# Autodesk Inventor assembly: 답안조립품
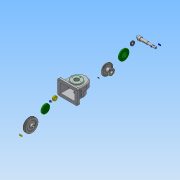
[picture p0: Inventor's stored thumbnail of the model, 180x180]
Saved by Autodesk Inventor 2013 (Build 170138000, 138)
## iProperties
Created: 2017-11
Part Number: 답안조립품
Document SubType Name: Assembly
Designer: Administrator
Author: Administrator
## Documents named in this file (14)
- C:\Users\Administrator\Desktop\471108V1027\답안조립품.iam
- C:\Users\Administrator\Desktop\471108V1027\키 - 6 x 6 x 22.ipt
- C:\Users\Administrator\Desktop\471108V1027\V-벨트풀리.ipt
- C:\Users\Administrator\Desktop\471108V1027\뒤커버.ipt
- C:\Users\Administrator\Desktop\471108V1027\멈춤나사 - M4 x 10.ipt
- 멈춤나사 - M4 x 10.ipt
- C:\Users\Administrator\Desktop\471108V1027\베어링 6002.ipt
- C:\Users\Administrator\Desktop\471108V1027\본체.ipt
- C:\Users\Administrator\Desktop\471108V1027\볼트 M3 x 8.ipt
- C:\Users\Administrator\Desktop\471108V1027\스퍼기어.ipt
- C:\Users\Administrator\Desktop\471108V1027\앞커버.ipt
- C:\Users\Administrator\Desktop\471108V1027\오일 실 15 30 7.ipt
- C:\Users\Administrator\Desktop\471108V1027\축.ipt
- C:\Users\Administrator\Desktop\471108V1027\키 - 5 x 5 x 18.ipt
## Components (1 placed, 1 different names)
1. V-벨트풀리:1
